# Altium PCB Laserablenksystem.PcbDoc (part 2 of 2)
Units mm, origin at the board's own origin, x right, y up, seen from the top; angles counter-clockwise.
Board outline 80 x 72 mm, 6 copper layers (L1 (Signal), L2 (GND), L3 (PWR), L4 (PWR), L5 (GND), L6 (Signal)), stack 1.637 mm thick; 152 components, 77 nets, 436 pads, 219 vias.
Unrouted connection lines stored in the file: 1.
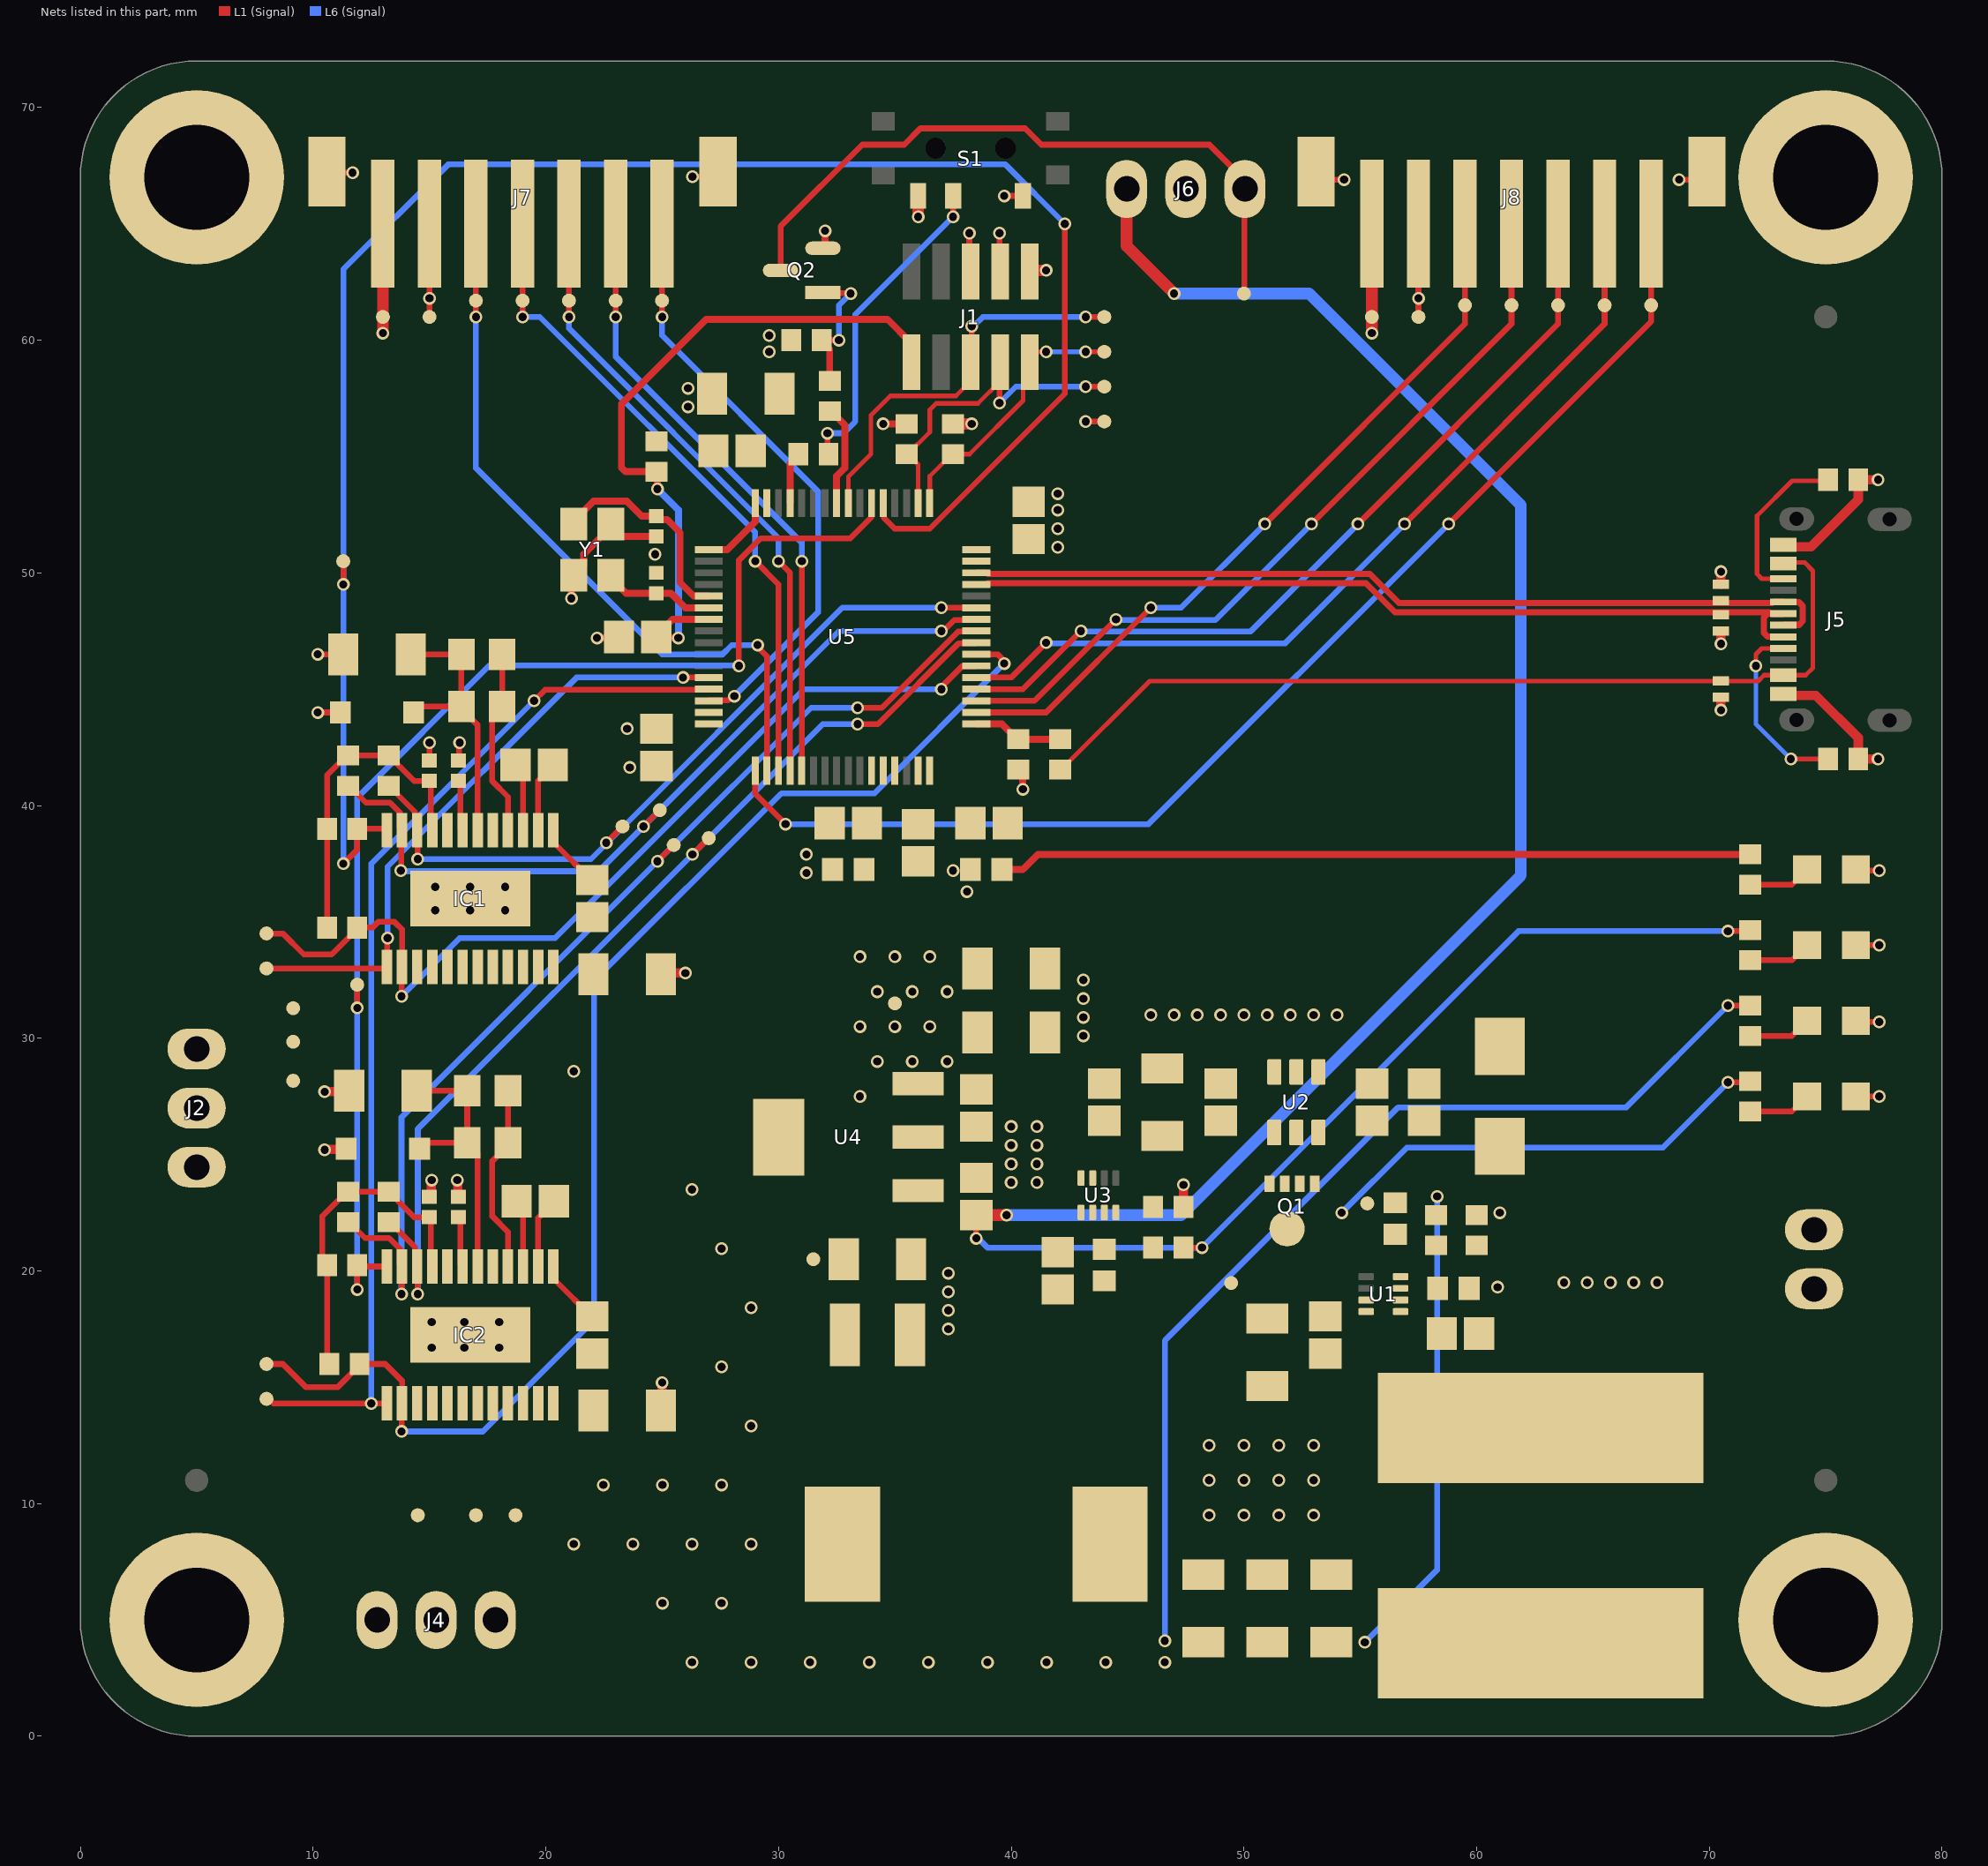
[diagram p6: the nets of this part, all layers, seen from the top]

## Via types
v1: diameter 0.55, hole 0.35, L1 (Signal) to L6 (Signal), tented both sides, 219 vias

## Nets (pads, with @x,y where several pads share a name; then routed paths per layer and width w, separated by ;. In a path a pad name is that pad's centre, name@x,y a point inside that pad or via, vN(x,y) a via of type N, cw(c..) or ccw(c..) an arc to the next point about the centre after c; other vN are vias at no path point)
BOOT0: R15.2 U5.61 | length 2.2
  L1 (Signal) w0.3: U5.61@30.5,53 30.5,54.7 30.85,55.05 R15.2@30.85,55.1
DIR_M1: IC1.14 R22.1 TP12.1 U5.38 | length 40.5
  L1 (Signal) w0.25: TP12.1@8,34.5 8.7,34.5 9.6,33.6 10.8,33.6 11.9,34.7 R22.1@11.9,34.75 11.904,34.754 12.554,34.754 12.8,35 13.5,35 13.825,34.675 IC1.14@13.825,33.062 13.813,33.05 13.813,31.813 v1(13.8,31.8) ; v1(37,45) 37.057,45.057 37.057,45.161 37.871,45.975 38.475,45.975 U5.38@38.5,46
  L6 (Signal) w0.25: v1(13.8,31.8) 16.3,34.3 20.4,34.3 31.1,45 v1(37,45)
DIR_M2: IC2.14 R28.1 TP17.1 U5.39 | length 58.7
  L1 (Signal) w0.25: TP17.1@8,16 8.7,16 9.7,15 11.05,15 12,15.95 R28.1@12,16 13.1,16 13.822,15.278 13.822,14.315 13.813,14.306 13.813,13.113 v1(13.8,13.1) ; U5.39@38.5,46.5 39.415,46.5 39.643,46.272 39.643,46.157 v1(39.7,46.1)
  L6 (Signal) w0.25: v1(13.8,13.1) 17.3,13.1 22.07,17.87 22.07,32.47 30.125,40.525 34.125,40.525 v1(39.7,46.1)
ENC1_CS: J7.3 TP25.1 U5.18 | length 31.6
  L1 (Signal) w0.25: v1(17,61) J7.3@17,65 ; v1(29.1,46.9) 29.1,46.819 29.5,46.419 U5.18@29.5,41.5
  L6 (Signal) w0.25: v1(17,61) 17,54.5 25,46.5 27.6,46.5 27.992,46.892 29.092,46.892 v1(29.1,46.9)
ENC1_MISO: J7.5 TP23.1 U5.20 | length 27.4
  L1 (Signal) w0.25: v1(21,61) J7.5@21,65 ; v1(30,50.5) 30.5,50 U5.20@30.5,41.5
  L6 (Signal) w0.25: v1(21,61) 21,60.5 30,51.5 v1(30,50.5)
ENC1_MOSI: J7.6 TP22.1 U5.21 | length 26.8
  L1 (Signal) w0.25: v1(23,61) J7.6@23,65 ; U5.21@31,41.5 v1(31,50.5)
  L6 (Signal) w0.25: v1(23,61) 23,59.3 31,51.3 v1(31,50.5)
ENC1_PWM: J7.7 TP21.1 U5.14 | length 25.7
  L1 (Signal) w0.25: v1(25,61) J7.7@25,65 ; U5.14@27,44.5 27.025,44.525 27.844,44.525 28.019,44.7 v1(28.1,44.7)
  L6 (Signal) w0.25: v1(25,61) 25,60.2 31.7,53.5 31.7,48.3 v1(28.1,44.7)
ENC1_SCK: J7.4 TP24.1 U5.19 | length 28.5
  L1 (Signal) w0.25: v1(19,61) J7.4@19,65 ; v1(29,50.5) 30,49.5 U5.19@30,41.5
  L6 (Signal) w0.25: v1(19,61) 19.742,61 29,51.742 v1(29,50.5)
ENC2_CS: J8.3 TP32.1 U5.34 | length 32
  L1 (Signal) w0.25: U5.34@38.5,44 41.5,44 v1(46,48.5) ; v1(50.9,52.1) 59.5,60.7 J8.3@59.5,64.75
  L6 (Signal) w0.25: v1(46,48.5) 47.3,48.5 v1(50.9,52.1)
ENC2_MISO: J8.5 TP30.1 U5.36 | length 35.6
  L1 (Signal) w0.25: U5.36@38.5,45 40.5,45 v1(43,47.5) ; v1(54.9,52.1) 63.5,60.7 J8.5@63.5,64.75
  L6 (Signal) w0.25: v1(43,47.5) 43.025,47.475 50.275,47.475 v1(54.9,52.1)
ENC2_MOSI: J8.6 TP29.1 U5.37 | length 37.4
  L1 (Signal) w0.25: U5.37@38.5,45.5 40,45.5 v1(41.5,47) ; v1(56.9,52.1) 65.5,60.7 J8.6@65.5,64.75
  L6 (Signal) w0.25: v1(41.5,47) 41.525,46.975 51.775,46.975 v1(56.9,52.1)
ENC2_PWM: J8.7 TP28.1 U5.17 | length 52.9
  L1 (Signal) w0.25: U5.17@29,41.5 29,40.5 v1(30.3,39.2) ; v1(58.8,52.1) 67.5,60.8 J8.7@67.5,64.75
  L6 (Signal) w0.25: v1(30.3,39.2) 45.9,39.2 v1(58.8,52.1)
ENC2_SCK: J8.4 TP31.1 U5.35 | length 33.8
  L1 (Signal) w0.25: U5.35@38.5,44.5 41,44.5 v1(44.5,48) ; v1(52.9,52.1) 61.5,60.7 J8.4@61.5,64.75
  L6 (Signal) w0.25: v1(44.5,48) 44.525,47.975 48.775,47.975 v1(52.9,52.1)
FG_M1: IC1.12 R21.2 TP11.1 U5.53 | length 81.8
  L1 (Signal) w0.25: v1(11.3,37.5) 11.9,38.1 R21.2@11.9,39 13.113,39 IC1.12@13.175,38.938 ; v1(11.3,49.5) TP11.1@11.3,50.5 ; U5.53@34.5,53 34.525,52.975 34.525,52.371 34.996,51.9 36.504,51.9 42.3,57.696 v1(42.3,65)
  L6 (Signal) w0.25: v1(11.3,37.5) v1(11.3,49.5) 11.3,63.042 15.808,67.55 39.75,67.55 v1(42.3,65)
FG_M2: IC2.12 R27.2 TP16.1 U5.54 | length 54.9
  L1 (Signal) w0.25: v1(11.9,19.2) R27.2@11.9,20.25 11.962,20.188 IC2.12@13.175,20.188 ; v1(11.9,31.3) TP16.1@11.9,32.3 ; v1(28.3,46) 28.3,50.542 29.243,51.486 33.089,51.486 33.975,52.371 33.975,52.975 U5.54@34,53
  L6 (Signal) w0.25: v1(11.9,19.2) 11.9,40.342 17.583,46.025 28.275,46.025 v1(28.3,46)
GND: C2.1 C4.1 C6.1 C7.1 C8.1 C9.1 C10.1 C11.1 C13.1 C14.1 C15.1 C16.1 C17.1 C18.1 C19.1 C20.1 C21.1 C22.1 C23.1 C24.1 C25.1 C26.1 C27.1 C28.1 C29.1 C30.1 C31.1 C32.1 C33.1 C36.2 C37.1 C38.2 C39.2 C42.2 C43.1 C44.2 C45.2 D1.2 D2.2 D3.2 D4.2 D5.2 D6.1 D7.1 D8.1 D9.1 D10.1 IC1.5 IC1.8 IC1.15 IC1.16 IC1.25 IC2.5 IC2.8 IC2.15 IC2.16 IC2.25 J1.3 J1.5 J3.2 J5.A1B12 J5.B1A12 J7.2 J7.8 J7.9 J8.2 J8.8 J8.9 Q2.2 R6.1 R8.1 R10.1 R12.1 R14.1 R29.1 R30.1 S1.1 ST1.1 ST2.1 ST3.1 ST4.1 TP8.1 TP20.1 TP27.1 U1.4 U2.2 U3.4 U4.2 U4.4 U5.15 U5.27 U5.31 U5.47 U5.63 Y1.2 Y1.4 | length 55.1
  L1 (Signal) w0.25: v1(10.2,44) D6.1@11.175,44 ; v1(10.2,46.5) C37.1@11.3,46.5 ; J7.8@10.6,67.25 10.65,67.2 v1(11.7,67.2) ; C39.2@15,41.94 v1(15,42.7) ; TP20.1@15,61 J7.2@15,65 ; C38.2@16.25,41.94 16.275,41.965 16.275,42.675 v1(16.3,42.7) ; v1(26.3,67.025) 27.175,67.025 J7.9@27.4,67.25 ; v1(38.2,64.6) 38.2,63 J1.5@38.25,62.95 ; v1(39.5,64.6) 39.5,62.97 J1.3@39.52,62.95 ; v1(39.7,66.2) S1.1@40.5,66.2 ; v1(43.2,56.5) TP8.1@44,56.5 ; J8.8@53.1,67 53.2,66.9 v1(54.3,66.9) ; TP27.1@57.5,61 J8.2@57.5,65 ; v1(68.7,66.9) 69.8,66.9 J8.9@69.9,67 ; D1.2@76.3,27.5 v1(77.3,27.5) ; D2.2@76.3,30.75 76.35,30.7 v1(77.3,30.7) ; D3.2@76.3,34 v1(77.3,34) ; D4.2@76.3,37.25 76.35,37.2 v1(77.3,37.2)
  L1 (Signal) w0.3: v1(21.1,48.9) 21.1,49.8 21.625,50.325 21.625,50.8 22.8,51.975 Y1.2@22.8,52.1 ; v1(22.2,47.2) 23.1,47.2 C33.1@23.15,47.25 ; Y1.2@22.8,51.985 23.225,51.56 C31.1@24.75,51.56 ; Q2.2@31.91,63.95 32,64.04 v1(32,64.7) ; v1(34.5,56.4) R14.1@35.5,56.4 ; R10.1@40.3,41.55 40.5,41.35 v1(40.5,40.7)
  L1 (Signal) w0.4: v1(10.5,25.2) 10.525,25.225 11.4,25.225 D7.1@11.425,25.25 ; v1(10.5,27.7) 11.5,27.7 C43.1@11.55,27.75 ; C45.2@15,23.19 15.071,23.261 15.071,23.871 v1(15.1,23.9) ; v1(16.2,23.9) 16.225,23.875 16.225,23.215 C44.2@16.25,23.19 ; C42.2@24.95,14 25,14.05 v1(25,15.2) ; C36.2@24.95,32.75 25,32.8 v1(26,32.8) ; R8.1@47.4,22.75 v1(47.4,23.7) ; v1(70.5,44.1) D10.1@70.5,44.65 ; v1(70.5,46.95) D8.1@70.5,47.5 ; D9.1@70.5,49.5 v1(70.5,50.05) ; J5.A1B12@73.175,44.8 73.242,44.733 74.573,44.733 76.4,42.906 R30.1@76.4,42 v1(77.25,42) ; J5.B1A12@73.175,51.2 73.252,51.123 74.372,51.123 76.4,53.151 R29.1@76.4,54 v1(77.25,54)
  other v1: 48.5,9.5 50,9.5 51.5,9.5 53,9.5 48.5,11 50,11 51.5,11 53,11 48.5,12.5 50,12.5 51.5,12.5 53,12.5 15.1,16.7 16.5,16.7 18,16.7 37.3,17.5 15.1,17.8 16.5,17.8 18,17.8 37.3,18.3 37.3,19.1 60.9,19.3 63.75,19.5 64.75,19.5 65.75,19.5 66.75,19.5 67.75,19.5 37.3,19.9 61,22.5 40,23.8 41.1,23.8 40,24.6 41.1,24.6 40,25.4 41.1,25.4 40,26.2 41.1,26.2 43.1,30.1 43.1,30.9 46,31 47,31 48,31 49,31 50,31 51,31 52,31 53,31 54,31 43.1,31.7 43.1,32.5 15.25,35.5 16.75,35.5 18.25,35.5 38.1,36.3 15.25,36.5 16.75,36.5 18.25,36.5 31.2,37.1 37.5,37.2 31.2,37.9 23.5,43.3 24.7,50.8 42,51.1 42,51.9 29.6,59.5 29.6,60.2 15,61.8 57.5,61.8
LASER-: J6.3 Q2.3 TP33.1 | length 29.4
  L1 (Signal) w0.25: Q2.3@30.09,63 30.09,64.89 33.6,68.4 35.4,68.4 36.1,69.1 40.6,69.1 41.3,68.4 48.515,68.4 50.034,66.881 J6.3@50.034,66.529 ; TP33.1@50,62 50.02,62.02 50.02,66.48 J6.3@50.04,66.5
LASER_C: R11.1 U5.57 | length 4.4
  L1 (Signal) w0.3: R11.1@32.2,56.95 32.25,56.95 32.85,56.35 32.85,54.511 32.5,54.161 U5.57@32.5,53
NetC1_1: C1.1 L1.1 U1.5
NetC1_2: C1.2 U1.6
NetC2_2: C2.2 C3.2 D5.1 J3.1 Q1.1 Q1.2 Q1.3 U2.3 U2.6
NetC3_1: C3.1 U2.1
NetC5_1: C5.1 R5.1 R6.2 U1.8
NetC11_2: C11.2 U1.7
NetC12_1: C12.1 L2.1 U3.5
NetC12_2: C12.2 U3.6
NetC21_2: C21.2 U3.7
NetC34_2: C34.2 IC1.1 | length 2.9
  L1 (Signal) w0.25: IC1.1@20.325,38.938 20.425,38.838 20.425,38.325 21.95,36.8 C34.2@22,36.8
NetC35_1: C35.1 IC1.2 | length 3.1
  L1 (Signal) w0.25: IC1.2@19.675,38.938 19.675,41.075 20.3,41.7 C35.1@20.3,41.75
NetC35_2: C35.2 IC1.3 | length 2.9
  L1 (Signal) w0.25: C35.2@18.7,41.75 19.025,41.425 IC1.3@19.025,38.938
NetC38_1: C38.1 IC1.7 | length 2.2
  L1 (Signal) w0.25: C38.1@16.25,41.06 16.338,40.973 16.338,39.025 IC1.7@16.425,38.938
NetC40_2: C40.2 IC2.1 | length 2.9
  L1 (Signal) w0.25: IC2.1@20.325,20.188 20.425,20.088 20.425,19.575 21.95,18.05 C40.2@22,18.05
NetC41_1: C41.1 IC2.2 | length 3.1
  L1 (Signal) w0.25: IC2.2@19.675,20.188 19.675,22.275 20.35,22.95 C41.1@20.35,23
NetC41_2: C41.2 IC2.3 | length 2.9
  L1 (Signal) w0.25: C41.2@18.75,23 19.025,22.725 IC2.3@19.025,20.188
NetC44_1: C44.1 IC2.7 | length 2.2
  L1 (Signal) w0.25: C44.1@16.25,22.31 16.338,22.222 16.338,20.275 IC2.7@16.425,20.188
NetD1_1: D1.1 R1.1 | length 2.7
  L1 (Signal) w0.25: R1.1@71.75,26.85 73.55,26.85 D1.1@74.2,27.5
NetD2_1: D2.1 R2.1 | length 2.7
  L1 (Signal) w0.25: R2.1@71.75,30.1 73.55,30.1 D2.1@74.2,30.75
NetD3_1: D3.1 R3.1 | length 2.7
  L1 (Signal) w0.25: R3.1@71.75,33.35 73.55,33.35 D3.1@74.2,34
NetD4_1: D4.1 R4.1 | length 2.7
  L1 (Signal) w0.25: R4.1@71.75,36.6 73.55,36.6 D4.1@74.2,37.25
NetJ5_A5: J5.A5 R30.2 | length 8
  L1 (Signal) w0.197: v1(72,46) 72,46.5 72.25,46.75 J5.A5@73.175,46.75 ; v1(73.5,42) R30.2@75.1,42
  L6 (Signal) w0.197: v1(72,46) 72,43.5 v1(73.5,42)
NetJ5_B5: J5.B5 R29.2 | length 7.4
  L1 (Signal) w0.197: J5.B5@73.175,49.75 72.25,49.75 72.051,49.949 72.051,52.449 73.551,53.949 75.049,53.949 R29.2@75.1,54
NetQ1_4: Q1.4 U2.5
NetQ2_1: Q2.1 R11.2 R12.2 | length 6
  L1 (Signal) w0.25: R12.2@31.85,60 v1(32.6,60) ; Q2.1@31.91,62.05 31.935,62.025 33.075,62.025 v1(33.1,62)
  L1 (Signal) w0.3: R12.2@31.85,59.95 32.2,59.6 R11.2@32.2,58.25
  L6 (Signal) w0.25: v1(32.6,60) 32.6,61.5 v1(33.1,62)
NetR7_1: R7.1 R8.2 U3.8
NetR15_1: R15.1 S1.2 | length 13.8
  L1 (Signal) w0.25: v1(32.1,56) 32.1,55.15 R15.1@32.15,55.1 ; v1(37.5,65.3) S1.2@37.5,66.2
  L6 (Signal) w0.25: v1(32.1,56) 32.8,56 33.3,56.5 33.3,61.1 v1(37.5,65.3)
NRST: C33.2 J1.10 R16.1 U5.7 | length 30.6
  L1 (Signal) w0.3: C33.2@24.75,47.25 24.8,47.2 v1(25.7,47.2) ; C33.2@24.75,47.3 25.45,48 U5.7@27,48 ; v1(24.8,53.6) 24.8,54.3 R16.1@24.75,54.35 23.426,54.35 23.25,54.526 23.25,57.25 26.9,60.9 34.68,60.9 35.71,59.87 J1.10@35.71,59.05
  L6 (Signal) w0.3: v1(24.8,53.6) 25.7,52.7 v1(25.7,47.2)
OSC_IN: C31.2 U5.5 Y1.3 | length 9.2
  L1 (Signal) w0.3: Y1.3@21.2,52.1 21.2,52.225 22.05,53.075 23.489,53.075 24.124,52.44 C31.2@24.75,52.44 24.9,52.29 25.21,52.29 25.773,51.727 25.773,49.589 26.361,49 U5.5@27,49
OSC_OUT: C32.2 U5.6 Y1.1 | length 4.8
  L1 (Signal) w0.3: Y1.1@22.8,49.9 22.8,49.775 23.455,49.12 C32.2@24.75,49.12 ; C32.2@24.77,49.12 25.38,49.12 26,48.5 U5.6@27,48.5
SCL_M1: IC1.10 R19.2 TP9.1 U5.43 | length 33.2
  L1 (Signal) w0.25: R19.2@13.25,40.85 13.3,40.85 13.6,40.55 13.6,40.5 14.375,39.725 14.375,39.038 IC1.10@14.475,38.938 14.488,38.926 14.488,37.712 v1(14.5,37.7) ; v1(22.6,38.4) TP9.1@23.3,39.1 ; v1(37,48.5) U5.43@38.5,48.5
  L6 (Signal) w0.25: v1(14.5,37.7) 21.942,37.7 32.742,48.5 v1(37,48.5)
SCL_M2: IC2.10 R25.2 TP14.1 U5.40 | length 44.4
  L1 (Signal) w0.25: R25.2@13.25,22.1 13.3,22.1 14.375,21.025 14.375,20.288 IC2.10@14.475,20.188 14.488,20.175 14.488,19.012 v1(14.5,19) ; v1(26.3,37.9) TP14.1@27,38.6 ; v1(33.4,43.5) 34.273,43.5 37.748,46.975 38.475,46.975 U5.40@38.5,47
  L6 (Signal) w0.25: v1(14.5,19) 14.5,26.1 v1(26.3,37.9) 31.9,43.5 v1(33.4,43.5)
SDA_M1: IC1.11 R20.2 TP10.1 U5.42 | length 35.5
  L1 (Signal) w0.25: R20.2@11.5,40.85 11.55,40.85 12.273,40.127 13.302,40.127 13.725,39.704 13.725,39.038 IC1.11@13.825,38.938 13.798,38.911 13.798,37.227 v1(13.77,37.2) ; v1(24.2,39.1) TP10.1@24.9,39.8 ; v1(37,47.5) 37.081,47.5 37.556,47.975 38.475,47.975 U5.42@38.5,48
  L6 (Signal) w0.25: v1(13.77,37.2) 13.795,37.175 22.275,37.175 32.6,47.5 v1(37,47.5)
SDA_M2: IC2.11 R26.2 TP15.1 U5.41 | length 46.7
  L1 (Signal) w0.25: R26.2@11.5,22.1 11.55,22.1 12.235,21.415 13.265,21.415 13.725,20.954 13.725,20.288 IC2.11@13.825,20.188 13.813,20.175 13.813,19.013 v1(13.8,19) ; v1(24.8,37.6) TP15.1@25.5,38.3 ; v1(33.4,44.2) 34.442,44.2 37.717,47.475 38.475,47.475 U5.41@38.5,47.5
  L6 (Signal) w0.25: v1(13.8,19) 13.8,26.6 v1(24.8,37.6) 31.4,44.2 v1(33.4,44.2)
SPEED_M1: IC1.13 TP13.1 U5.12 | length 26.7
  L1 (Signal) w0.25: TP13.1@8,33 13.113,33 IC1.13@13.175,33.062 13.188,33.075 13.188,34.288 v1(13.2,34.3) ; v1(25.9,45.5) U5.12@27,45.5
  L6 (Signal) w0.25: v1(13.2,34.3) 13.2,37.372 21.328,45.5 v1(25.9,45.5)
SPEED_M2: IC2.13 TP18.1 U5.13 | length 46
  L1 (Signal) w0.25: TP18.1@8.095,14.5 8.295,14.3 13.163,14.3 IC2.13@13.175,14.312 ; v1(19.5,44.5) 19.975,44.975 26.975,44.975 U5.13@27,45
  L6 (Signal) w0.25: v1(12.5,14.3) 12.5,37.5 v1(19.5,44.5)
SW_M1: IC1.4 R17.1 R18.1 | length 8
  L1 (Signal) w0.25: R18.1@18.125,46.5 R17.1@18.125,44.25 17.7,43.825 17.7,41.046 18.375,40.371 IC1.4@18.375,38.938
SW_M2: IC2.4 R23.1 R24.1 | length 8.1
  L1 (Signal) w0.25: IC2.4@18.375,20.188 18.375,21.671 17.7,22.346 17.7,24.725 18.375,25.4 R24.1@18.375,25.5 R23.1@18.375,27.75
SWCLK: J1.4 R14.2 TP5.1 U5.50 | length 15.5
  L1 (Signal) w0.197: R14.2@35.5,55.1 R14.2@35.55,55.1 ; U5.50@36,53 36,54.65 R14.2@35.55,55.1 ; J1.4@39.52,59.05 39.52,58.23 38.568,57.278 36.778,57.278 36.5,57 36.5,56.05 R14.2@35.55,55.1
  L1 (Signal) w0.25: v1(39.5,57.3) 39.5,59.03 J1.4@39.52,59.05 ; v1(43.2,58) TP5.1@44,58
  L6 (Signal) w0.25: v1(39.5,57.3) 40.2,58 v1(43.2,58)
SWDIO: J1.2 R13.1 TP6.1 U5.49 | length 11.8
  L1 (Signal) w0.197: U5.49@36.5,53 36.5,54.15 37.45,55.1 38.207,55.1 40.509,57.402 40.509,58.769 J1.2@40.79,59.05 40.79,59.219 41.071,59.5 v1(41.5,59.5) ; v1(43.2,59.5) TP6.1@44,59.5
  L6 (Signal) w0.197: v1(41.5,59.5) v1(43.2,59.5)
SWO: J1.6 TP7.1 U5.56 | length 17.3
  L1 (Signal) w0.197: U5.56@33,53 33,54.133 33.966,55.099 33.966,56.766 34.8,57.6 37.62,57.6 38.25,58.23 J1.6@38.25,59.05
  L1 (Signal) w0.25: J1.6@38.25,59.05 38.3,59.1 v1(38.3,60.6) ; v1(43.2,61) TP7.1@44,61
  L6 (Signal) w0.25: v1(38.3,60.6) 38.381,60.6 38.781,61 v1(43.2,61)
U_M1: IC1.17 IC1.18 J2.3 TP34.1
U_M2: IC2.17 IC2.18 J4.3 TP37.1
USB_N: D8.2 J5.A7 J5.B7 U5.45 | length 37.6
  L1 (Signal) w0.27: U5.45@38.5,49.5 38.95,49.5 39.002,49.552 55.247,49.552 56.497,48.302 70.5,48.302 72.567,48.302 ; J5.A7@72.698,48.235 73.16,48.235 J5.A7@73.175,48.25 72.516,48.25 72.34,48.075 72.34,47.423 72.498,47.265 73.16,47.265 J5.B7@73.175,47.25
USB_P: D9.2 J5.A6 J5.B6 U5.46 | length 37.7
  L1 (Signal) w0.27: U5.46@38.5,50 38.95,50 39.002,49.948 55.411,49.948 56.661,48.698 70.5,48.698 72.698,48.698 72.75,48.75 J5.B6@73.175,48.75 73.19,48.735 73.852,48.735 74.01,48.577 74.01,47.923 73.852,47.765 73.19,47.765 J5.A6@73.175,47.75
USB_SENS: R9.1 R10.2 U5.33 | length 3.9
  L1 (Signal) w0.3: U5.33@38.5,43.5 39.6,43.5 40.25,42.85 R10.2@40.3,42.85 R9.1@42.1,42.85
USB_VBUS: D10.2 J5.A4B9 J5.B4A9 R9.2 | length 39.8
  L1 (Signal) w0.197: R9.2@42.1,41.55 42.15,41.55 45.95,45.35 67,45.35 72.1,45.35 72.35,45.6 J5.A4B9@73.175,45.6 74.136,45.6 74.445,45.909 74.445,50.091 74.095,50.442 73.215,50.442 J5.B4A9@73.175,50.4
V3P3_M1: C39.1 IC1.9 R19.1 R20.1 R21.1 R22.2 | length 13.9
  L1 (Signal) w0.25: R22.2@10.6,34.75 R21.1@10.6,39 10.6,41.3 11.45,42.15 R20.1@11.5,42.15 R19.1@13.25,42.15 ; R19.1@13.3,42.15 13.6,41.85 13.6,41.8 14.34,41.06 C39.1@15,41.06 15.063,40.998 15.063,39.001 IC1.9@15.125,38.938
V3P3_M2: C45.1 IC2.9 R25.1 R26.1 R27.1 R28.2 | length 14.1
  L1 (Signal) w0.25: R28.2@10.7,16 10.6,16.1 R27.1@10.6,20.25 10.4,20.45 10.4,22.35 11.45,23.4 R26.1@11.5,23.4 R25.1@13.25,23.4 ; R25.1@13.3,23.4 13.6,23.1 13.6,23.05 14.34,22.31 C45.1@15,22.31 15.063,22.247 15.063,20.25 IC2.9@15.125,20.188
V_M1: IC1.19 IC1.20 J2.2 TP35.1
V_M2: IC2.19 IC2.20 J4.2 TP38.1
VCC3V3: C18.2 C19.2 C20.2 C22.2 C23.2 C24.2 C25.2 C26.2 C27.2 C28.2 C29.2 C30.2 J1.1 J6.2 J7.1 J8.1 R4.2 R13.2 R16.2 S1.3 TP4.1 TP19.1 TP26.1 U4.3 U5.1 U5.16 U5.28 U5.29 U5.32 U5.48 U5.64 | length 47.5
  L1 (Signal) w0.3: U5.1@27,51 27.8,51 29,52.2 U5.64@29,53 ; C29.2@39.6,37.25 40.5,37.25 41.15,37.9 R4.2@71.75,37.9
  L1 (Signal) w0.5: v1(13,60.3) J7.1@13,65 ; v1(36,65.3) S1.3@36,66.2 ; R13.2@37.5,56.4 v1(38.3,56.4) ; J1.1@40.79,62.95 40.84,63 v1(41.5,63) ; v1(55.5,60.3) J8.1@55.5,65
  other v1: 33.5,27.5 34.25,29 35.75,29 37.25,29 33.5,30.5 35,30.5 36.5,30.5 34.25,32 35.75,32 37.25,32 33.5,33.5 35,33.5 36.5,33.5 23.609,41.634 42,52.7 42,53.4 26.109,57.134 26.109,57.934
VCC5: C15.2 C16.2 C17.2 J6.1 L2.2 R3.2 R7.2 TP3.1 U4.1 | length 110.2
  L1 (Signal) w0.25: v1(38.5,21.4) C17.2@38.5,22.4 ; R7.2@47.4,21 v1(48.2,21) ; v1(70.8,34.6) 71.7,34.6 R3.2@71.75,34.65
  L1 (Signal) w0.5: C17.2@38.5,22.4 v1(39.8,22.4) ; J6.1@44.96,66.5 44.96,64.04 v1(47,62)
  L6 (Signal) w0.25: v1(38.5,21.4) 38.581,21.4 38.981,21 v1(48.2,21) 61.8,34.6 v1(70.8,34.6)
  L6 (Signal) w0.5: v1(39.8,22.4) 47.3,22.4 61.9,37 61.9,52.9 52.8,62 v1(47,62)
VCC10: C5.2 C8.2 C9.2 C10.2 C34.1 C36.1 C40.1 C42.1 IC1.23 IC1.24 IC2.23 IC2.24 L1.2 R2.2 R5.2 TP2.1 | length 64.5
  L1 (Signal) w0.25: v1(70.8,31.4) R2.2@71.75,31.4
  L6 (Signal) w0.25: v1(46.6,4.1) 46.6,17 56.63,27.03 66.43,27.03 v1(70.8,31.4) ; v1(55.197,4.039) 58.3,7.142 v1(58.3,23.2)
  other v1: 26.28,3.18 28.82,3.18 31.36,3.18 33.9,3.18 36.44,3.18 38.98,3.18 41.52,3.18 44.06,3.18 46.6,3.18 25.01,5.72 27.55,5.72 21.2,8.26 23.74,8.26 26.28,8.26 28.82,8.26 22.47,10.8 25.01,10.8 27.55,10.8 28.82,13.34 27.55,15.88 28.82,18.42 27.55,20.96 26.28,23.5 21.2,28.58
VCC24: C4.2 C6.2 C7.2 C13.2 C14.2 Q1.5-6-7-8 R1.2 TP1.1 U1.3 U2.4 U3.3 | length 19.9
  L1 (Signal) w0.25: v1(70.8,28.1) 71.7,28.1 R1.2@71.75,28.15
  L6 (Signal) w0.25: v1(54.2,22.5) 57,25.3 68,25.3 v1(70.8,28.1)
VREG_M1: C37.2 D6.2 IC1.6 R17.2 R18.2 | length 12.1
  L1 (Signal) w0.25: C37.2@14.2,46.5 R18.2@16.375,46.5 R17.2@16.375,44.25 14.575,44.25 D6.2@14.325,44 ; R17.2@16.375,44.15 17.075,43.45 IC1.6@17.075,38.938
VREG_M2: C43.2 D7.2 IC2.6 R23.2 R24.2 | length 12.1
  L1 (Signal) w0.25: C43.2@14.45,27.75 R23.2@16.625,27.75 R24.2@16.625,25.5 ; D7.2@14.575,25.25 14.825,25.5 R24.2@16.625,25.5 ; IC2.6@17.075,20.188 17.075,25.05 R24.2@16.625,25.5
W_M1: IC1.21 IC1.22 J2.1 TP36.1
W_M2: IC2.21 IC2.22 J4.1 TP39.1
pads on no net: FD1.0 FD2.0 FD3.0 J1.7 J1.8 J1.9 J5.A8 J5.B8 J5.S S1.M S1.MH U1.1 U1.2 U3.1 U3.2 U5.2 U5.3 U5.4 U5.8 U5.9 U5.10 U5.11 U5.22 U5.23 U5.24 U5.25 U5.26 U5.30 U5.44 U5.51 U5.52 U5.55 U5.58 U5.59 U5.60 U5.62

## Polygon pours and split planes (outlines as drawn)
GND on L1 (Signal) "GND_L01_P007" (solid, pour order 7): 31.9,36.7 30.9,36.7 30.9,38.8 30.9,39.8 31.7,40.6 33.6,40.6 33.833,40.833 33.833,42.1 34.163,42.1 34.163,40.563 33.9,40.3 33.3,40.3 32.9,39.9 32.9,36.7
VCC3V3 on L1 (Signal) "L1 (Signal)-VCC3V3" (solid, pour order 46): 33,27 40,27 40,34.5 41.4,35.9 41.4,39.8 41.2,40 40.5,40 40.1,40.4 39.7,40.4 39.2,40.9 37.9,40.9 36.7,42.1 36.347,42.1 36.347,40.894 37.041,40.2 39.2,40.2 39.2,38 39.1,37.9 39.1,35.35 38.75,35 37,35 36.7,35.3 36.7,38.3 34.6,38.3 34.6,39.9 35.154,40.454 35.154,42.1 34.341,42.1 34.341,40.441 33.8,39.9 33.2,39.9 33.2,36.7 33,36.5
GND on L1 (Signal) "GND_L01_P044" (solid, pour order 44): 14.148,15.926 14.239,15.834 14.239,13.564 15.359,13.564 15.359,15.759 15.627,16.027 19.355,16.027 19.355,18.466 18.234,18.466 17.958,18.845 17.958,20.93 17.5,20.93 17.5,18.845 17.266,18.466 16.334,18.466 16,18.845 16,20.93 15.545,20.93 15.545,18.845 15.166,18.466 14.148,18.466
VCC3V3 on L1 (Signal) "VCC3V3_L01_P003" (solid, pour order 3): 25.7,56.2 24.257,56.2 24.257,55.243 24.306,55.194 26.4,55.194 26.4,54.1 26.9,53.6 28.6,53.6 28.8,53.4 28.8,52.4 29.2,52.4 29.2,53.7 28.9,54 28.1,54 27.9,54.2 27.9,58.7 26.4,58.7 25.7,58 25.7,56.9
GND on L1 (Signal) "GND_L01_P004" (solid, pour order 4): 42.3,52.2 42.3,50.7 41.6,50.7 39.981,50.7 39.646,50.343 37.9,50.343 37.9,50.655 39.255,50.655 39.9,51.3 39.9,52.2
VCC24 on L1 (Signal) "VCC24_L01_P016" (solid, pour order 16): 49,18.2 49,19.1 49,24.1 48.3,24.8 43.9,24.8 43.7,24.6 43.7,23.6 43.3,23.6 43.3,24.6 43.2,24.8 43.2,27.2 50,27.2 50.6,26.6 51.6,26.6 51.6,25.2 50.3,25.2 50.3,23.1 54.5,23.1 54.5,19.2 54.797,18.903 55.601,18.903 55.601,18.598 54.798,18.598 54.5,18.3 54.5,17.3 49.9,17.3
NetC12_2 on L1 (Signal) "NETC12_2_L01_P025" (solid, pour order 25): 43.652,22.9 43.652,22.052 42.8,21.2 42.8,20.1 41.1,20.1 41.1,21.6 42.758,21.6 43.347,22.189 43.347,22.9
NetC21_2 on L1 (Signal) "NETC21_2_L01_P024" (solid, pour order 24): 43.84,22.9 43.84,21.94 43.3,21.4 43.3,20.3 44.7,20.3 44.7,21.6 44.7,21.4 44.16,21.94 44.16,22.9
NetC1_1 on L1 (Signal) "NETC1_1_L01_P020" (solid, pour order 20): 69.875,16.553 68.3,18.2 59.4,18.2 59.4,16.2 57.2,16.2 57.075,16.325 57.075,18.4 56.388,18.4 56.388,16.488 55.625,15.725 55.625,10.75 69.875,10.75
GND on L1 (Signal) "GND_L01_P041" (solid, pour order 41): 57,29.4 56.7,29.7 52.8,29.7 52.553,29.453 52.553,27.991 51.943,27.991 51.943,29.457 51.7,29.7 50.5,29.7 50.3,29.5 50.3,27.5 42.6,27.5 42.6,25 43.2,24.4 43.2,23.6 43,23.4 37.6,23.4 37.6,24.4 37.3,24.7 32.8,24.7 31.4,23.3 28.7,23.3 28.7,28.3 31.1,28.3 32.9,26.5 40.2,26.5 40.5,26.8 40.5,34.4 42.5,34.4 44.9,32 62.5,32 63.1,31.4 63.1,27.5 57,27.5
VCC5 on L1 (Signal) "VCC5_L01_P027" (solid, pour order 27): 34.375,5.75 34.375,21.7 39.5,21.7 39.5,23.1 37.496,23.1 37.3,23.296 37.3,24.1 34.1,24.1 31.125,21.125 31.125,5.75
VCC10 on L1 (Signal) "VCC10_L01_P021" (solid, pour order 21): 55.9,23.6 55.617,23.317 54.889,23.317 54.889,22.504 55.593,22.504 55.9,22.3 57.531,22.3 57.531,21.92 59,21.92 59,23.6
VCC10 on L1 (Signal) "VCC10_L01_P022" (solid, pour order 22): 19.439,9.561 21,8 28,1 69.875,1 69.875,6.5 55.625,6.5 55.625,5.425 55,4.8 47,4.8 29.5,4.8 29.5,21 23,27.5 23,36 19.685,36 19.685,33.807 19.439,33.807 19.439,32.309 20.5,32.309 20.5,26.5 27,20 27,12.7 26.3,12 23.7,12 23,12.7 23,17.12 19.685,17.12 19.685,15.062 19.439,15.062
GND on L1 (Signal) "GND_L01_P042" (solid, pour order 42): 14.148,34.722 14.243,34.627 14.243,32.319 15.356,32.319 15.356,34.256 15.873,34.773 19.355,34.773 19.355,37.236 18.364,37.236 17.958,37.642 17.958,39.675 17.494,39.675 17.494,37.594 17.136,37.236 16.364,37.236 16.013,37.587 16.013,39.675 15.542,39.675 15.542,37.642 15.136,37.236 14.148,37.236
GND on L1 (Signal) "GND_L01_P040" (solid, pour order 40): 35,21.5 37.1,21.5 37.8,20.8 37.8,15.9 37.7,15.8 34.9,15.8 34.9,21.4
GND on L1 (Signal) "GND_L01_P038" (solid, pour order 38): 61.3,19.9 61.5,20.1 61.5,21.7 61.28,21.92 59.4,21.92 59.4,23 61.5,23 63,21.5 64.3,20.2 71.2,20.2 77.7,20.2 77.7,18 72,18 71.3,18.7 59.2,18.7 59.2,19.9
GND on L1 (Signal) "GND_L01_P039" (solid, pour order 39): 54.6,17 54.8,17.2 54.8,18.4 55.6,18.4 55.6,17 54.8,16.2 54.8,6 47,6 47,6.1 47,14.8 43.3,18.5 43.3,20.1 45,20.1 48.1,17
U_M1 on L1 (Signal) "U_M1_L01_P035" (solid, pour order 35): 8.712,30.9 8.712,31.8 9.576,31.8 9.576,30.9 14.7,30.9 15.537,31.737 15.537,33.8 16.662,33.8 16.662,32.162 15,30.5 8.681,30.5 6.581,28.4 2.9,28.4 2.9,30.9
W_M1 on L1 (Signal) "W_M1_L01_P037" (solid, pour order 37): 10,29.6 5.9,25.5 2.9,25.5 2.9,23.2 8.7,23.2 8.7,27.1 10.8,29.2 16.3,29.2 19.253,32.153 19.253,33.8 18.136,33.8 18.136,31.836 15.9,29.6
V_M1 on L1 (Signal) "V_M1_L01_P036" (solid, pour order 36): 10,30.3 8.8,30.3 6.7,28.2 6.5,28.2 2.9,28.2 2.9,25.8 5.861,25.8 9.855,29.794 15.594,29.794 17.95,32.15 17.95,33.8 16.833,33.8 16.833,31.833 15.3,30.3
U_M2 on L1 (Signal) "U_M2_L01_P034" (solid, pour order 34): 15.545,15.062 15.545,11.545 11.5,7.5 11.5,2.9 13.9,2.9 13.9,7.9 16.662,10.662 16.662,15.062
V_M2 on L1 (Signal) "V_M2_L01_P033" (solid, pour order 33): 17.976,15.062 16.84,15.062 16.84,10.54 14.199,7.899 14.199,2.9 16.4,2.9 16.4,7.7 17.976,9.276
W_M2 on L1 (Signal) "W_M2_L01_P032" (solid, pour order 32): 19.265,15.062 18.136,15.062 18.136,9.136 16.7,7.7 16.7,2.9 19.265,2.9
VCC3V3 on L1 (Signal) "VCC3V3_L01_P001" (solid, pour order 1): 23.9,42.3 23.2,42.3 23.2,41 25.8,41 27.6,41 27.6,43.663 26.363,43.663 26.2,43.5 26.2,42.6 25.9,42.3
GND on L1 (Signal) "GND_L01_P000" (solid, pour order 0): 23.9,44.15 23.2,44.15 23.2,42.5 25.75,42.5 25.875,42.625 25.875,43.5 26.225,43.85 27.6,43.85 27.6,44.15 23.95,44.15
NetC2_2 on L1 (Signal) "NETC2_2_L01_P013" (solid, pour order 13): 51.75,27.25 51.75,29.25 50.75,29.25 50.75,27 52.25,27 52.75,26.5 52.75,24.1 51.5,24.1 51.5,23.25 54.5,23.25 54.5,24.054 60.946,24.054 64.426,20.574 77.75,20.574 77.75,24.5 68,24.5 65.25,27.25 59.5,27.25
NetC12_1 on L1 (Signal) "NETC12_1_L01_P026" (solid, pour order 26): 40.8,21.8 41.2,22.2 43.155,22.2 43.155,22.9 40.4,22.9 40.3,22.8 40.3,5.75 45.9,5.75 45.9,14.1 43,17 43,19.9 41,19.9 40.8,20.1
NetR7_1 on L1 (Signal) "NETR7_1_L01_P023" (solid, pour order 23): 44.3,22.9 44.9,22.9 45.5,23.5 46.7,23.5 46.7,20.3 45.4,20.3 45.4,22 45.3,22.1 44.3,22.1
NetC1_2 on L1 (Signal) "NETC1_2_L01_P019" (solid, pour order 19): 56.388,18.9 57.35,18.9 57.35,18.544 57.567,18.3 59.2,18.3 59.2,16.5 57.5,16.5 57.5,18.115 57.041,18.6 56.388,18.6
NetC11_2 on L1 (Signal) "NETC11_2_L01_P018" (solid, pour order 18): 56.388,19.4 57.4,19.4 57.5,19.45 57.5,20 58.9,20 58.9,18.6 57.7,18.6 57.5,18.8 57.5,19.05 57.4,19.1 56.388,19.1
NetC5_1 on L1 (Signal) "NETC5_1_L01_P017" (solid, pour order 17): 55.8,22.1 57.3,22.1 57.3,21.7 61,21.7 61,20.3 60.9,20.2 57.3,20.2 57.3,19.6 56.388,19.6 56.388,20.412 55.8,21
NetC3_1 on L1 (Signal) "NETC3_1_L01_P015" (solid, pour order 15): 52.9,29.1 56.5,29.1 56.5,27.4 52.9,27.4
NetQ1_4 on L1 (Signal) "NETQ1_4_L01_P014" (solid, pour order 14): 51.9,26.5 51.9,25 51,25 50.75,24.75 50.75,23.25 51.25,23.25 51.3,23.3 51.3,24.4 52.4,24.4 52.6,24.6 52.6,26.5
GND on L1 (Signal) "GND_L01_P011" (solid, pour order 11): 24.3,51.9 24.3,49.7 25.2,49.7 25.2,51.9
GND on L1 (Signal) "GND_L01_P006" (solid, pour order 6): 37.1,38.5 37.2,38.4 37.2,36 38.8,36 38.8,38.4 39,38.6 39,40 36.6,40 36.158,40.442 36.158,42.1 35.839,42.1 35.839,40.439 35.3,39.9 35.3,38.5
VCC3V3 on L1 (Signal) "VCC3V3_L01_P005" (solid, pour order 5): 42.3,53.8 42.3,52.3 39.8,52.3 39.5,52 39.5,51.2 39.144,50.844 37.9,50.844 37.9,51.156 38.756,51.156 39.1,51.5 39.1,52.4 39.9,53.2 39.9,53.8 41.6,53.8
GND on L1 (Signal) "GND_L01_P002" (solid, pour order 2): 29.2,58.7 29.2,60.5 30.1,60.5 30.988,60.5 30.988,56.888 30.7,56.6 30.1,56.6 29.7,56.2 29.7,52.4 29.3,52.4 29.3,54.2 29.1,54.4 28.2,54.4 28.1,54.5 28.1,56.1 29.2,57.2
VCC3V3 on L3 (PWR) "VCC3V3_L03_P049" (solid, pour order 49): 32,27 32,39 23,39 23,48 10,61 10,70 59,70 59,61 44,46 44,27
VCC10 on L3 (PWR) "VCC10_L03_P055" (solid, pour order 55): 70,10 31,10 31,21 25,27 25,36 19,36 19,1 70,1
VCC3V3 on L4 (PWR) "VCC3V3_L04_P054" (solid, pour order 54): 10,70 10,61 23,48 23,39 32,39 32,27 44,27 44,46 59,61 59,70
VCC10 on L4 (PWR) "VCC10_L04_P056" (solid, pour order 56): 19,36 25,36 25,27 31,21 31,10 70,10 70,1 19,1
GND on L2 (GND) (split plane): 75.294,71.482 75.586,71.453 75.876,71.406 76.163,71.339 76.444,71.253 76.719,71.15 76.987,71.029 77.246,70.89 77.496,70.735 77.734,70.564 77.962,70.377 78.176,70.176 78.377,69.962 78.564,69.734 78.735,69.496 78.89,69.246 79.029,68.987 79.15,68.719 79.253,68.444 79.339,68.163 79.406,67.876 79.453,67.586 79.482,67.294 79.491,67.018 79.49,67 79.49,5 79.491,4.982 79.482,4.706 79.453,4.414 79.406,4.124 79.339,3.837 79.253,3.556 79.15,3.281 79.029,3.013 78.89,2.754 78.735,2.504 78.564,2.266 78.377,2.038 78.176,1.824 77.962,1.623 77.734,1.436 77.496,1.265 77.246,1.11 76.987,0.971 76.719,0.85 76.444,0.747 76.163,0.661 75.876,0.594 75.586,0.547 75.294,0.518 75.018,0.509 75,0.51 5,0.51 4.982,0.509 4.706,0.518 4.414,0.547 4.124,0.594 3.837,0.661 3.556,0.747 3.281,0.85 3.013,0.971 2.754,1.11 2.504,1.265 2.266,1.436 2.038,1.623 1.824,1.824 1.623,2.038 1.436,2.266 1.265,2.504 1.11,2.754 0.971,3.013 0.85,3.281 0.747,3.556 0.661,3.837 0.594,4.124 0.547,4.414 0.518,4.706 0.509,4.982 0.51,5 0.51,50 0.51,67 0.509,67.018 0.518,67.294 0.547,67.586 0.594,67.876 0.661,68.163 0.747,68.444 0.85,68.719 0.971,68.987 1.11,69.246 1.265,69.496 1.436,69.734 1.623,69.962 1.824,70.176 2.038,70.377 2.266,70.564 2.504,70.735 2.754,70.89 3.013,71.029 3.281,71.15 3.556,71.253 3.837,71.339 4.124,71.406 4.414,71.453 4.706,71.482 4.982,71.491 5,71.49 75,71.49 75.018,71.491
GND on L5 (GND) (split plane): 75.294,71.482 75.586,71.453 75.876,71.406 76.163,71.339 76.444,71.253 76.719,71.15 76.987,71.029 77.246,70.89 77.496,70.735 77.734,70.564 77.962,70.377 78.176,70.176 78.377,69.962 78.564,69.734 78.735,69.496 78.89,69.246 79.029,68.987 79.15,68.719 79.253,68.444 79.339,68.163 79.406,67.876 79.453,67.586 79.482,67.294 79.491,67.018 79.49,67 79.49,5 79.491,4.982 79.482,4.706 79.453,4.414 79.406,4.124 79.339,3.837 79.253,3.556 79.15,3.281 79.029,3.013 78.89,2.754 78.735,2.504 78.564,2.266 78.377,2.038 78.176,1.824 77.962,1.623 77.734,1.436 77.496,1.265 77.246,1.11 76.987,0.971 76.719,0.85 76.444,0.747 76.163,0.661 75.876,0.594 75.586,0.547 75.294,0.518 75.018,0.509 75,0.51 5,0.51 4.982,0.509 4.706,0.518 4.414,0.547 4.124,0.594 3.837,0.661 3.556,0.747 3.281,0.85 3.013,0.971 2.754,1.11 2.504,1.265 2.266,1.436 2.038,1.623 1.824,1.824 1.623,2.038 1.436,2.266 1.265,2.504 1.11,2.754 0.971,3.013 0.85,3.281 0.747,3.556 0.661,3.837 0.594,4.124 0.547,4.414 0.518,4.706 0.509,4.982 0.51,5 0.51,50 0.51,67 0.509,67.018 0.518,67.294 0.547,67.586 0.594,67.876 0.661,68.163 0.747,68.444 0.85,68.719 0.971,68.987 1.11,69.246 1.265,69.496 1.436,69.734 1.623,69.962 1.824,70.176 2.038,70.377 2.266,70.564 2.504,70.735 2.754,70.89 3.013,71.029 3.281,71.15 3.556,71.253 3.837,71.339 4.124,71.406 4.414,71.453 4.706,71.482 4.982,71.491 5,71.49 75,71.49 75.018,71.491

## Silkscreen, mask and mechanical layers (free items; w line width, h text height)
Top Overlay:
  drawing of 56 lines, arcs and shapes, not listed
  text "ENC1" at 20.348,71.448 h0.81 r180
  text "5V" at 45.648,71.448 h0.81 r180
  text "3V3" at 48.648,71.448 h0.81 r180
  text "L-" at 50.748,71.448 h0.81 r180
  text "ENC2" at 62.948,71.448 h0.81 r180
  text "+" at 33.598,69.983 h0.81 r180
  text "3.3" at 78.848,36.152 h0.81 r90
  text "5" at 78.848,33.752 h0.81 r90
  text "10" at 78.848,30.152 h0.81 r90
  text "U1" at 0.452,29.848 h0.81 r270
  text "V1" at 0.452,27.348 h0.81 r270
  text "24" at 78.848,26.852 h0.81 r90
  text "W1" at 0.452,24.848 h0.81 r270
  text "24V" at 79.348,20.952 h0.81 r90
  text "GND" at 79.348,17.852 h0.81 r90
  text "U2" at 12.052,0.352 h0.81
  text "V2" at 14.652,0.352 h0.81
  text "W2" at 17.452,0.352 h0.81
Mechanical 1:
  the board outline again, w0.254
